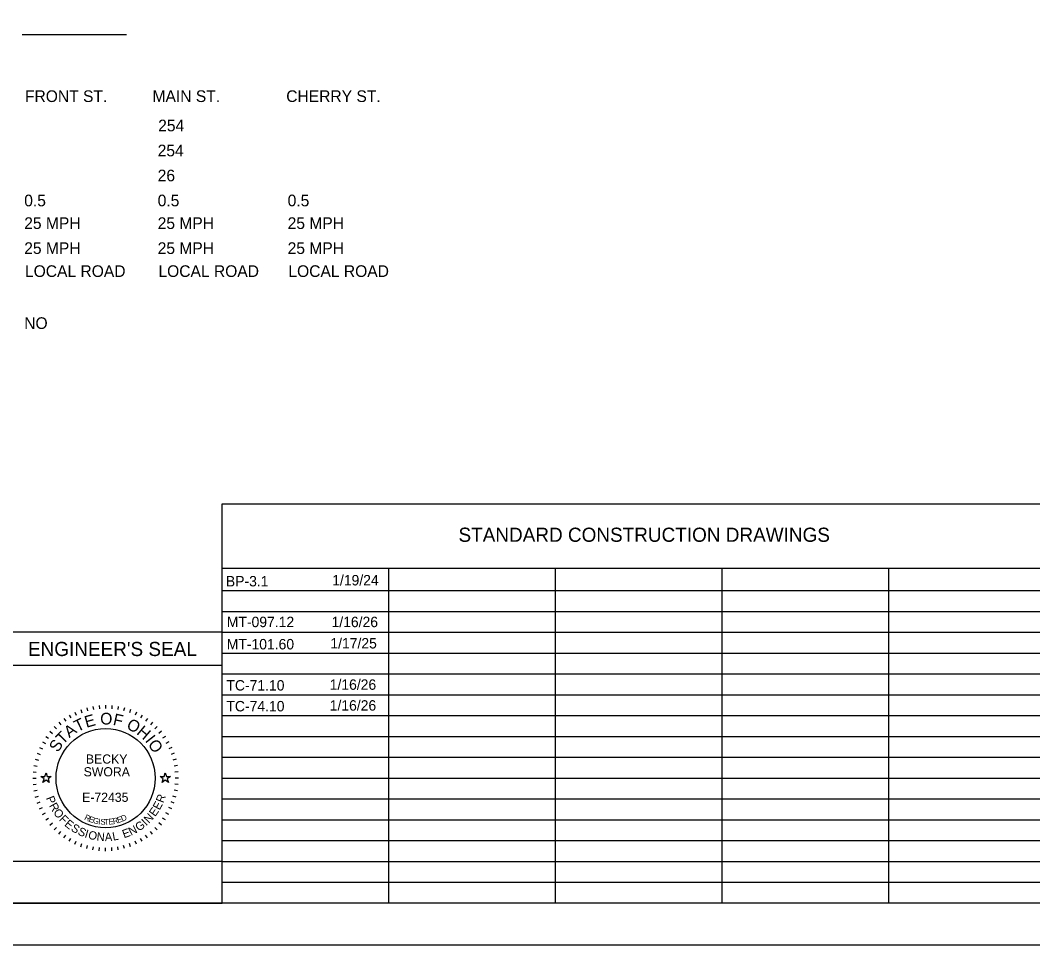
# Model space of a CAD drawing. Extents: x 0 to 34, y 0 to 22.
# Drawn here: x 7.94 to 20.09, y 0 to 11.1 of the extents above; entities that cross this region are included whole.
import ezdxf

# ---------------------------------------------------------------- set-up
doc = ezdxf.new("R2010")
doc.units = 0
for name, color, linetype in [('Default', 7, 'Continuous'), ('SH_Border', 7, 'Continuous'), ('SH_Cut_Line', 7, 'Continuous'), ('SH_Data', 7, 'Continuous'), ('SH_Seal', 7, 'Continuous'), ('SH_Text', 7, 'Continuous')]:
    doc.layers.add(name, color=color, linetype=linetype)

msp = doc.modelspace()

# ---------------------------------------------------------------- linework, layer by layer
at = {"layer": 'SH_Border'}
msp.add_lwpolyline([(1.5, 21.5), (33.5, 21.5), (33.5, 0.5), (1.5, 0.5)], close=True, dxfattribs=at)
at = {"layer": 'SH_Cut_Line'}
msp.add_lwpolyline([(0, 0), (34, 0), (34, 22), (0, 22)], close=True, dxfattribs=at)
at = {"layer": 'SH_Data'}
for p, q in [((9.214, 10.922), (7.964, 10.922)), ((10.364, 5.291), (23.814, 5.291)), ((10.364, 0.5), (10.364, 5.291)), ((10.364, 4.52), (23.814, 4.52)), ((12.364, 0.5), (12.364, 4.52)), ((14.364, 0.5), (14.364, 4.52)), ((16.364, 0.5), (16.364, 4.52)), ((18.364, 0.5), (18.364, 4.52)), ((10.364, 4.25), (23.814, 4.25)), ((10.364, 4), (23.814, 4)), ((10.364, 3.75), (7.564, 3.75)), ((10.364, 3.75), (23.814, 3.75)), ((10.364, 0.5), (10.364, 3.75)), ((10.364, 3.5), (23.814, 3.5)), ((10.364, 3.35), (7.564, 3.35)), ((10.364, 3.25), (23.814, 3.25)), ((10.364, 3), (23.814, 3)), ((10.364, 2.75), (23.814, 2.75)), ((10.364, 2.5), (23.814, 2.5)), ((10.364, 2.25), (23.814, 2.25)), ((10.364, 2), (23.814, 2)), ((10.364, 1.75), (23.814, 1.75)), ((10.364, 1.5), (23.814, 1.5)), ((10.364, 1.25), (23.814, 1.25)), ((10.364, 1), (23.814, 1)), ((10.364, 0.75), (23.814, 0.75)), ((10.364, 0.5), (7.564, 0.5))]:
    msp.add_line(p, q, dxfattribs=at)
msp.add_lwpolyline([(10.364, 0.5), (10.364, 1), (7.564, 1), (7.564, 0.5)], close=True, dxfattribs=at)
at = {"layer": 'SH_Seal'}
for p, q in [((8.665, 2.822), (8.679, 2.784)), ((8.738, 2.845), (8.748, 2.806)), ((8.812, 2.861), (8.819, 2.822)), ((8.888, 2.871), (8.891, 2.831)), ((8.964, 2.875), (8.964, 2.835)), ((9.04, 2.871), (9.037, 2.831)), ((9.116, 2.861), (9.109, 2.822)), ((9.191, 2.845), (9.18, 2.806)), ((9.263, 2.822), (9.25, 2.784)), ((8.462, 2.716), (8.485, 2.684)), ((8.527, 2.757), (8.547, 2.723)), ((8.594, 2.793), (8.611, 2.756)), ((9.334, 2.793), (9.317, 2.756)), ((9.402, 2.757), (9.382, 2.723)), ((9.466, 2.716), (9.443, 2.684)), ((8.294, 2.562), (8.325, 2.536)), ((8.345, 2.618), (8.374, 2.59)), ((8.402, 2.67), (8.427, 2.639)), ((9.527, 2.67), (9.501, 2.639)), ((9.583, 2.618), (9.555, 2.59)), ((9.635, 2.562), (9.604, 2.536)), ((8.206, 2.437), (8.241, 2.417)), ((8.247, 2.501), (8.28, 2.478)), ((9.681, 2.501), (9.648, 2.478)), ((9.722, 2.437), (9.687, 2.417)), ((8.171, 2.369), (8.207, 2.352)), ((9.757, 2.369), (9.721, 2.352)), ((8.119, 2.226), (8.158, 2.216)), ((8.142, 2.299), (8.18, 2.285)), ((9.786, 2.299), (9.749, 2.285)), ((9.809, 2.226), (9.771, 2.216)), ((8.093, 2.076), (8.132, 2.072)), ((8.103, 2.151), (8.142, 2.145)), ((9.826, 2.151), (9.787, 2.145)), ((9.836, 2.076), (9.796, 2.072)), ((8.089, 2), (8.129, 2)), ((9.839, 2), (9.799, 2)), ((8.093, 1.923), (8.132, 1.927)), ((8.103, 1.848), (8.142, 1.855)), ((9.826, 1.848), (9.787, 1.855)), ((9.836, 1.923), (9.796, 1.927)), ((8.119, 1.773), (8.158, 1.783)), ((8.142, 1.7), (8.18, 1.714)), ((9.786, 1.7), (9.749, 1.714)), ((9.809, 1.773), (9.771, 1.783)), ((8.171, 1.63), (8.207, 1.647)), ((8.206, 1.562), (8.241, 1.582)), ((9.722, 1.562), (9.687, 1.582)), ((9.757, 1.63), (9.721, 1.647)), ((8.247, 1.498), (8.28, 1.521)), ((8.294, 1.437), (8.325, 1.463)), ((9.635, 1.437), (9.604, 1.463)), ((9.681, 1.498), (9.648, 1.521)), ((8.345, 1.381), (8.374, 1.409)), ((8.402, 1.329), (8.427, 1.36)), ((9.527, 1.329), (9.501, 1.36)), ((9.583, 1.381), (9.555, 1.409)), ((8.462, 1.283), (8.485, 1.316)), ((8.527, 1.242), (8.547, 1.276)), ((8.594, 1.207), (8.611, 1.243)), ((9.334, 1.207), (9.317, 1.243)), ((9.402, 1.242), (9.382, 1.276)), ((9.466, 1.283), (9.443, 1.316)), ((8.665, 1.177), (8.679, 1.215)), ((8.738, 1.154), (8.748, 1.193)), ((8.812, 1.138), (8.819, 1.177)), ((8.888, 1.128), (8.891, 1.168)), ((8.964, 1.125), (8.964, 1.165)), ((9.04, 1.128), (9.037, 1.168)), ((9.116, 1.138), (9.109, 1.177)), ((9.191, 1.154), (9.18, 1.193)), ((9.263, 1.177), (9.25, 1.215))]:
    msp.add_line(p, q, dxfattribs=at)
for points in [[(8.188, 2.02), (8.235, 2.02), (8.249, 2.064), (8.264, 2.02), (8.311, 2.02), (8.273, 1.992), (8.287, 1.947), (8.249, 1.975), (8.211, 1.947), (8.226, 1.992)], [(9.618, 2.02), (9.665, 2.02), (9.679, 2.064), (9.694, 2.02), (9.741, 2.02), (9.703, 1.992), (9.717, 1.947), (9.679, 1.975), (9.641, 1.947), (9.656, 1.992)]]:
    msp.add_lwpolyline(points, close=True, dxfattribs=at)
msp.add_circle((8.964, 2), 0.595, dxfattribs=at)

# ---------------------------------------------------------------- texts
at = {"layer": 'Default'}
for s, p in [('BP-3.1', (10.408, 4.301)), ('1/19/24', (11.684, 4.313)), ('MT-101.60', (10.418, 3.545)), ('1/17/25', (11.662, 3.556)), ('TC-71.10', (10.414, 3.051)), ('1/16/26', (11.654, 3.06)), ('TC-74.10', (10.414, 2.801)), ('1/16/26', (11.654, 2.81))]:
    msp.add_text(s, height=0.125, dxfattribs=at).set_placement(p)
at = {"layer": 'SH_Data'}
msp.add_text("ENGINEER'S SEAL", height=0.17, dxfattribs=at).set_placement((8.032, 3.465))
at = {"layer": 'SH_Seal'}
for s, height, rotation, p in [('T', 0.14, 25.7167, (8.626, 2.551)), ('E', 0.14, 15.7571, (8.733, 2.603)), ('O', 0.14, 359.7812, (8.899, 2.644)), ('F', 0.14, 347.4362, (9.045, 2.641)), ('O', 0.14, 332.2586, (9.204, 2.601)), ('T', 0.14, 46.4344, (8.453, 2.396)), ('A', 0.14, 36.4747, (8.528, 2.478)), ('H', 0.14, 319.9136, (9.327, 2.536)), ('S', 0.14, 57.1924, (8.392, 2.301)), ('I', 0.14, 308.367, (9.431, 2.448)), ('O', 0.14, 303.1491, (9.466, 2.408)), ('P', 0.1, 291.494, (8.246, 1.762)), ('R', 0.1, 298.7311, (8.283, 1.671)), ('E', 0.1, 61.9951, (9.612, 1.609)), ('R', 0.1, 69.2322, (9.656, 1.695)), ('O', 0.1, 306.4666, (8.33, 1.588)), ('N', 0.1, 47.0224, (9.484, 1.45)), ('E', 0.1, 54.758, (9.558, 1.531)), ('F', 0.1, 314.7068, (8.399, 1.498)), ('E', 0.1, 321.4393, (8.462, 1.434)), ('R', 0.07, 334.487, (8.702, 1.505)), ('E', 0.07, 341.04, (8.755, 1.48)), ('G', 0.07, 347.4752, (8.806, 1.461)), ('I', 0.07, 353.7858, (8.873, 1.446)), ('S', 0.07, 356.8926, (8.9, 1.442)), ('T', 0.07, 3.0061, (8.95, 1.438)), ('E', 0.07, 6.0117, (9.003, 1.441)), ('R', 0.07, 11.9184, (9.057, 1.447)), ('E', 0.07, 17.6836, (9.114, 1.46)), ('D', 0.07, 23.3052, (9.165, 1.477)), ('G', 0.1, 35.0469, (9.362, 1.357)), ('I', 0.1, 43.287, (9.451, 1.421)), ('S', 0.1, 328.6764, (8.539, 1.375)), ('S', 0.1, 335.9134, (8.621, 1.326)), ('I', 0.1, 343.1505, (8.705, 1.289)), ('O', 0.1, 346.8859, (8.748, 1.275)), ('N', 0.1, 355.1261, (8.853, 1.251)), ('A', 0.1, 2.8617, (8.956, 1.243)), ('L', 0.1, 10.0987, (9.054, 1.249)), ('E', 0.1, 20.0742, (9.185, 1.277)), ('N', 0.1, 27.3113, (9.269, 1.307))]:
    msp.add_text(s, height=height, rotation=rotation, dxfattribs=at).set_placement(p)
for s, p in [('BECKY ', (8.727, 2.174)), ('SWORA', (8.7, 2.021)), ('E-72435', (8.682, 1.715))]:
    msp.add_text(s, height=0.11, dxfattribs=at).set_placement(p)
at = {"layer": 'SH_Text'}
for s, height, p in [('FRONT ST.', 0.14, (7.996, 10.115)), ('MAIN ST.', 0.14, (9.527, 10.115)), ('CHERRY ST.', 0.14, (11.132, 10.115)), ('254', 0.14, (9.595, 9.763)), ('254', 0.14, (9.589, 9.463)), ('26', 0.14, (9.589, 9.163)), ('0.5', 0.14, (7.987, 8.863)), ('0.5', 0.14, (9.589, 8.863)), ('0.5', 0.14, (11.149, 8.863)), ('25 MPH', 0.14, (7.987, 8.591)), ('25 MPH', 0.14, (9.589, 8.591)), ('25 MPH', 0.14, (11.149, 8.591)), ('25 MPH', 0.14, (7.987, 8.291)), ('25 MPH', 0.14, (9.589, 8.291)), ('25 MPH', 0.14, (11.149, 8.291)), ('LOCAL ROAD', 0.14, (7.996, 8.015)), ('LOCAL ROAD', 0.14, (9.598, 8.015)), ('LOCAL ROAD', 0.14, (11.158, 8.015)), ('NO', 0.14, (7.987, 7.391)), ('STANDARD CONSTRUCTION DRAWINGS', 0.17, (13.2, 4.836)), ('MT-097.12', 0.125, (10.419, 3.812)), ('1/16/26', 0.125, (11.676, 3.812))]:
    msp.add_text(s, height=height, dxfattribs=at).set_placement(p)

doc.saveas('drawing.dxf')
